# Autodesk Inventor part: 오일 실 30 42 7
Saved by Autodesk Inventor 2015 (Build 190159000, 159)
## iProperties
Created: 2025-06
Part Number: 오일 실 30 42 7
Material: 일반
Document SubType Name: Modeling
Designer: 104
Density: 1 g/cm^3
Appearance: 기본값
Author: 104
Author: jhkim
Description: 오일 실 - 스프링 장착, 금속 케이스 SM
Creation Date: 2025-05-23
Sending System: Autodesk Inventor 2026
Preprocessor: ST-DEVELOPER v20.1
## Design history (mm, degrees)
node "오일 실 30 42 71"
body "Solid1"
node "기준1"
